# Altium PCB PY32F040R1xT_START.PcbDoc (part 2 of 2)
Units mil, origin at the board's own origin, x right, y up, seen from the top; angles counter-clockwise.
Board outline 1771.65 x 3925.12 mil, 2 copper layers (Top Layer, Bottom Layer), stack 21 mil thick; 156 components, 167 nets, 616 pads, 288 vias.
Unrouted connection lines stored in the file: 5.
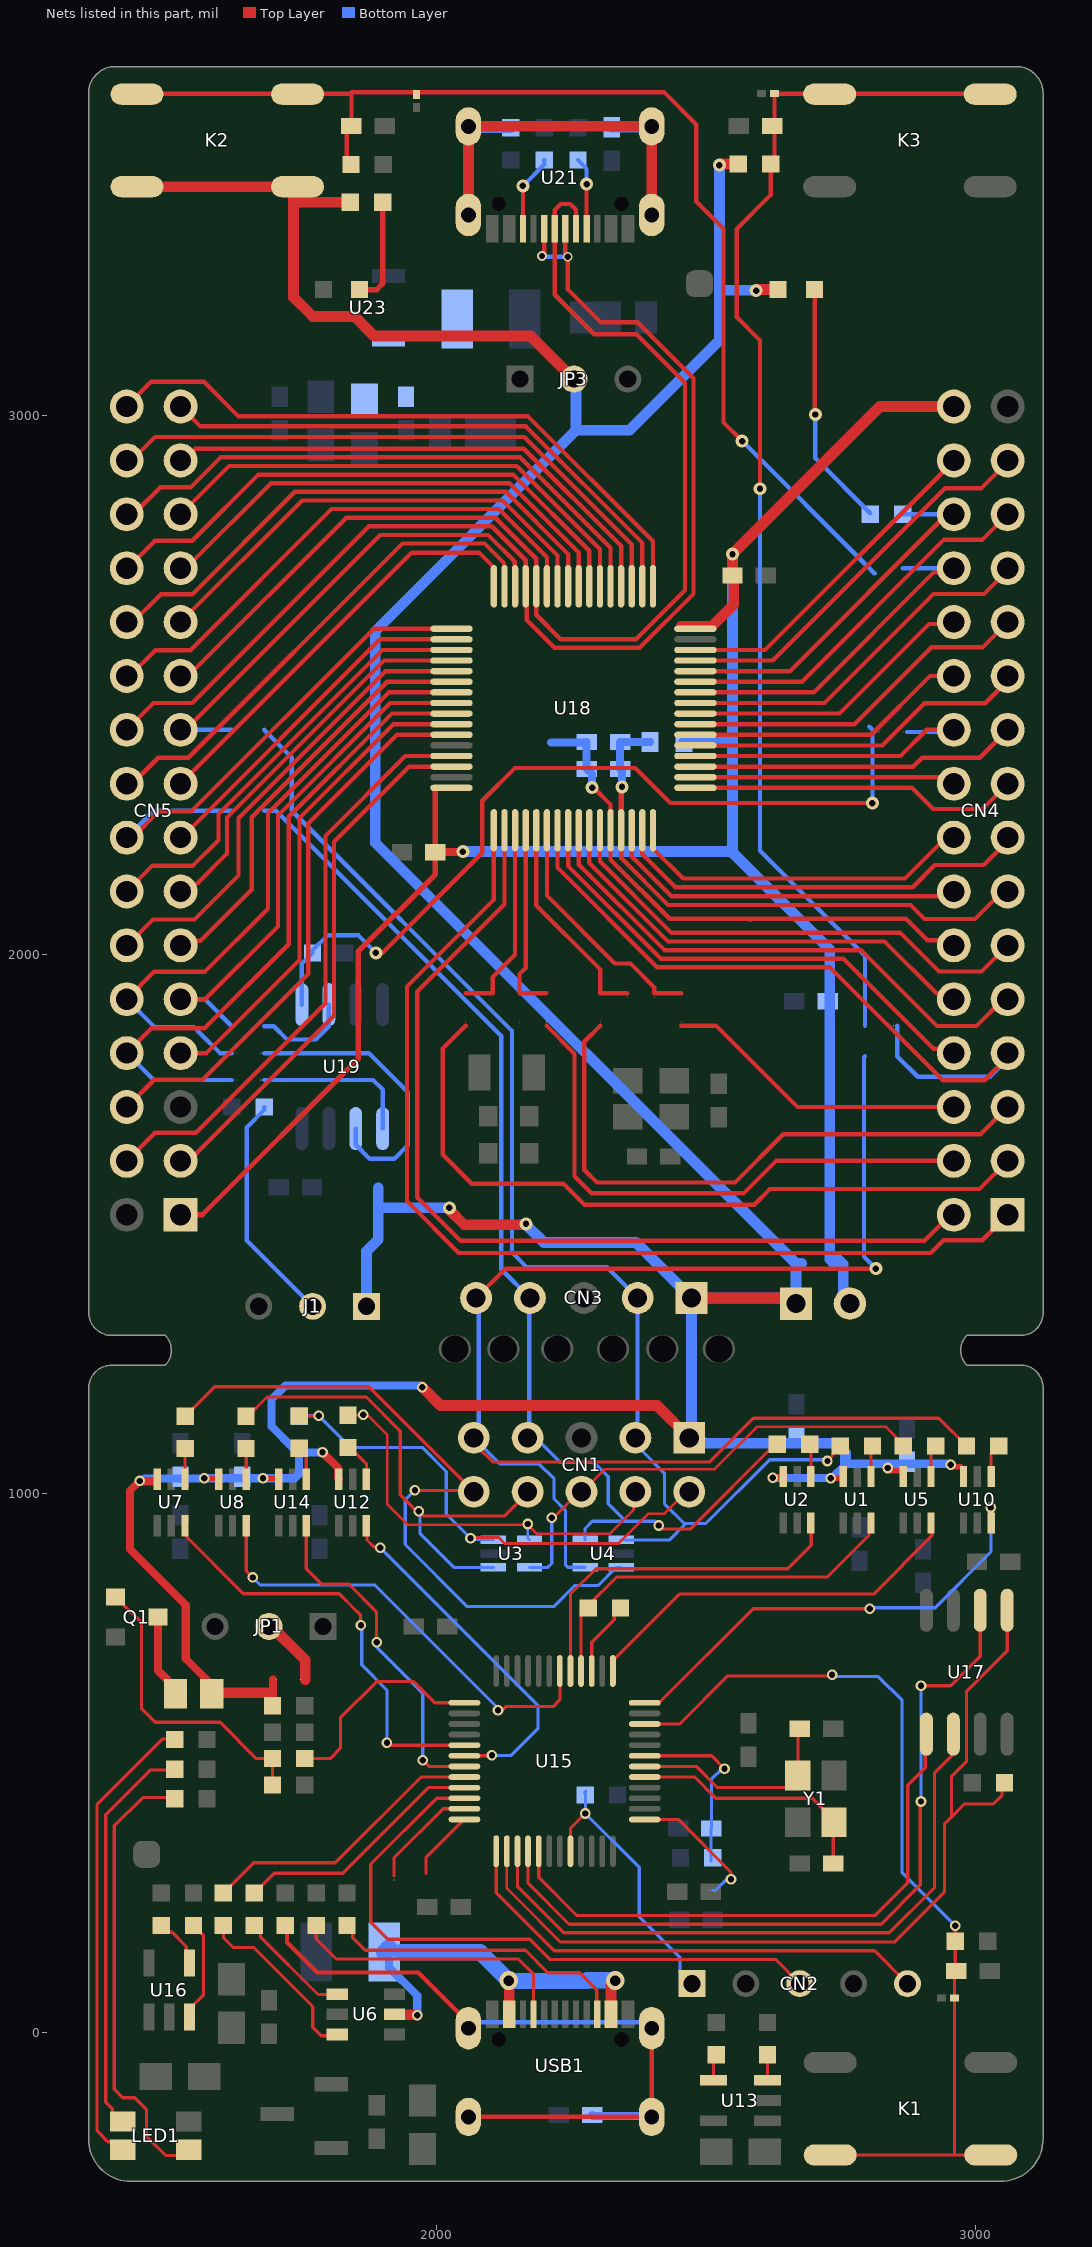
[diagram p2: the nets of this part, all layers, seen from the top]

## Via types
v1: diameter 24, hole 12, Top Layer to Bottom Layer, tented both sides, 117 vias
v2: diameter 19.68, hole 11.81, Top Layer to Bottom Layer, tented both sides, 109 vias
v3: diameter 19.68, hole 11.81, Top Layer to Bottom Layer, 41 vias
v4: diameter 35, hole 20, Top Layer to Bottom Layer, tented both sides, 15 vias
v5: diameter 17.72, hole 11.81, Top Layer to Bottom Layer, tented both sides, 2 vias
v6: diameter 30, hole 15, Top Layer to Bottom Layer, tented both sides, 2 vias
v7: diameter 40, hole 20, Top Layer to Bottom Layer, tented both sides, 2 vias

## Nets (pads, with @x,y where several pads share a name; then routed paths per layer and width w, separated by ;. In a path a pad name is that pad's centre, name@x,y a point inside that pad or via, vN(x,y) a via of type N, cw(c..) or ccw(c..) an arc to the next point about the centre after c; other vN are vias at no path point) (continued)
NetC34_2: C34.2 K3.1 R51.2 R52.1 U20.1 | length 2260.3
  Top Layer w8: v1(2600.24,2864.39) 2600.24,3139.79 2557.01,3183.01 2557.01,3346.47 2620,3409.45 2620,3464.12 R51.2@2620,3467.24 ; R51.2@2623.12,3464.12 2627.3,3468.3 U20.1@2627.3,3598 2627.95,3597.35 3026.9,3597.35 K3.1@3027.55,3596.7
  Bottom Layer w8: v1(2600.24,2864.39) 2600.24,2192.48 2795,1997.72 2795,1868
NetC35_2: C35.2 K2.1 R53.1 R54.2 U22.1 | length 2245.4
  Top Layer w8: K2.1@1444,3596.7 1444.65,3597.35 1742,3597.35 1842,3597.35 C35.2@1842,3538 ; R54.2@1833.14,3468.87 1833.14,3529.14 C35.2@1842,3538 ; R54.2@1841,3466.26 R54.2@1853,3454.26 ; v1(2567.19,2952.83) 2532.54,2987.49 2532.54,3346.86 2481.86,3397.53 2481.86,3540.74 2422.03,3600.57 1842.28,3600.57 1842,3600.29 C35.2@1842,3538
  Bottom Layer w8: v1(2567.19,2952.83) 2800.42,2719.61 2801,2719.61 2801,2719 2812.39,2707.61 2813,2707.61
NetC38_2: C38.2 C39.2 FUSE2.2 U23.3
NetC40_2: C40.2 R7.1 USB1.1 USB1.2 USB1.3 USB1.4 | length 1406.9
  Top Layer w8: R7.1@1719,198 1722.29,194.71 1722.29,166.87 1778.64,110.52 1965.97,110.52 2059.12,17.37 USB1.1@2059.12,7.29 ; USB1.3@2059.12,-157.27 USB1.4@2399.28,-157.27 USB1.2@2399.28,7.29
  Bottom Layer w8: USB1.1@2070.04,18.21 USB1.2@2388.36,18.21
  Bottom Layer w15: C40.2@2289,-154 2290.64,-155.64 2397.64,-155.64 USB1.4@2399.28,-157.27
  Bottom Layer w20: USB1.1@2059.12,7.29 USB1.1@2070.04,18.21 ; USB1.2@2388.36,18.21 USB1.2@2399.28,7.29
NetC41_2: C41.2 R57.2 U21.1 U21.2 U21.3 U21.4 | length 832
  Top Layer w20: U21.2@2059.12,3372.52 U21.4@2059.12,3537.08 U21.3@2399.28,3537.08 U21.1@2399.28,3372.52 U21.1@2399.28,3380.89
  Bottom Layer w20: U21.4@2059.12,3537.08 2061.7,3534.5 R57.2@2137.5,3534.5 ; C41.2@2325,3535.5 2397.69,3535.5 U21.3@2399.28,3537.08
NetJ1_2: J1.2 R41.1 | length 433.9
  Bottom Layer w8: R41.1@1680,1717 1680,1711.41 1647.74,1679.15 1647.74,1469.39 J1.2@1770,1347.13
NetLED1_2: LED1.2 R8.1 | length 846.1
  Top Layer w6: R8.1@1514,433 1511.67,435.33 1454.33,435.33 1402,383 1402,-106 1417.8,-121.8 1439.86,-121.8 1461.53,-143.47 1461.53,-192.84 1497.82,-229.13 1529.08,-229.13 LED1.2@1540.02,-218.18
NetLED1_3: LED1.3 R5.1 | length 884.3
  Top Layer w6: LED1.3@1398.28,-218.48 LED1.3@1412.98,-233.18 ; LED1.3@1417.98,-218.18 1403.28,-203.48 1390.09,-203.48 1370,-183.39 1370,423.34 1490.59,543.93 1513.07,543.93 R5.1@1514,543
NetLED1_4: LED1.4 R4.1 | length 755.1
  Top Layer w6: LED1.4@1410.66,-178.5 1398.36,-166.19 1398.36,-142.26 1386,-129.91 1386,403.34 1469.39,486.73 1512.73,486.73 R4.1@1514,488
NetLED2_VDD*_1: LED2_VDD*.1 R59.1 | length 198.6
  Top Layer w10: LED2_VDD*.1@1857,3234 1889,3234 1900,3245 R59.1@1900,3396
NetLED3_PB2_2: LED3_PB2.2 R46.1 | length 460.1
  Top Layer w8: LED3_PB2.2@2701.06,3235.88 2702.06,3234.88 2702.06,3005.95 v1@2703.04,3004.97
  Bottom Layer w8: v1@2703.04,3004.97 2703.04,2920.9 R46.1@2805.06,2818.88
  other v1: 2703.22,3002.23
NetQ1_1: Q1.1 R18.1 R19.2 | length 559
  Top Layer w6: Q1.1@1404,807.8 1405.97,807.8 1417.72,796.06 1417.72,794.23 1452.46,759.49 1452.46,600.34 1477.86,574.94 1598.45,574.94 1665.61,507.78 R18.1@1695.53,507.78 ; R19.2@1695.52,458.88 R18.1@1695.52,507.77
NetQ1_3: Q1.3 R14.1 | length 166.5
  Top Layer w6: Q1.3@1479.49,767.15 Q1.3@1482.74,770.4 ; R14.1@1515.54,628 R14.1@1515.54,633.91
  Top Layer w15: Q1.3@1482.74,770.4 1482.74,671.28 1515.54,638.49 R14.1@1515.54,628
NetR1_2: R1.2 USB1.A5 | length 530.2
  Top Layer w6: R1.2@1776.49,197.99 1776.49,172.82 1813.51,135.79 2151.58,135.79 2180.13,107.25 USB1.A5@2180.13,33.03
NetR2_1: R2.1 U1.4 | length 57.9
  Top Layer w6: U1.4@2806.23,1031.31 2806.23,1085.02 R2.1@2809.21,1088
NetR3_1: R3.1 USB1.B5 | length 566
  Top Layer w6: R3.1@1834,198 1844.31,187.69 1844.31,175.34 1867.85,151.8 2165.11,151.8 2206.66,110.24 2265.55,110.24 2297.17,78.62 2297.17,33.82 USB1.B5@2298.1,32.89
NetR6_1: R6.1 U2.4 | length 57.8
  Top Layer w6: R6.1@2692.06,1088 2694.8,1085.27 U2.4@2694.8,1031.31
NetR9_1: R9.1 U5.4 | length 60.3
  Top Layer w6: U5.4@2917.66,1031.31 2917.66,1079.3 R9.1@2926.35,1088
NetR10_1: R10.1 U6.3 | length 332.9
  Top Layer w6: R10.1@1604,198 1604.77,197.23 1604.77,174.69 1622.41,157.05 1660.8,157.05 1770.24,47.61 1770.24,8.87 1785.63,-6.52 1813.74,-6.52 U6.3@1815.53,-4.72
NetR11_1: R11.1 U6.1 | length 227.7
  Top Layer w6: R11.1@1662.75,203 1673.15,192.6 1673.15,176.68 1780,69.83 U6.1@1825.97,69.83
NetR12_1: R12.1 U7.4 | length 59
  Top Layer w6: R12.1@1527.55,1083 1533.14,1077.41 U7.4@1533.14,1026.31
NetR13_1: R13.1 U8.4 | length 60.8
  Top Layer w6: R13.1@1634.94,1083.02 R13.1@1644.82,1073.14 ; U8.4@1646.86,1026.31 R13.1@1646.86,1073.12
NetR17_1: R17.1 U10.4 | length 62.7
  Top Layer w6: U10.4@3029.08,1031.31 3029.08,1073.59 R17.1@3043.49,1088
NetR21_1: R21.1 U12.4 | length 75.3
  Top Layer w6: R21.1@1835.63,1085.11 1839.62,1085.11 1869.71,1055.03 U12.4@1869.71,1026.31
NetR23_2: R23.2 U13.4 | length 49.6
  Top Layer w6: U13.4@2514,-89.5 2514,-47 R23.2@2519,-42
NetR24_2: R24.2 U13.3 | length 47.5
  Top Layer w6: U13.3@2614,-89.5 R24.2@2614,-42
NetR25_1: R25.1 U14.4 | length 62.8
  Top Layer w6: R25.1@1745.2,1083.7 1758.28,1070.62 U14.4@1758.28,1026.31
NetR26_2: R26.2 U15.1 | length 256.3
  Top Layer w6: U15.1@2386.32,394.73 2448.18,394.73 2546.46,296.45 v3(2546.46,283.88)
  Bottom Layer w6: 2512.34,262.83 2517.61,262.83 2538.66,283.88 v3(2546.46,283.88)
NetR28_2: R28.2 U16.4 | length 96.1
  Top Layer w6: R28.2@1489,198 1501,186 1508.44,186 1535.5,158.94 1535.5,134 U16.4@1541.5,128
NetR29_2: R29.2 U16.3 | length 188.5
  Top Layer w6: U16.3@1541.5,28 1541.5,43 1567.56,69.06 1567.56,178.68 1561,185.24 1561,186 R29.2@1549,198
NetR30_1: R30.1 U15.36 | length 129.6
  Top Layer w6: 1980.21,294.75 1980.21,323.26 U15.36@2051.68,394.73
NetR32_1: R32.1 U15.35 | length 201.4
  Top Layer w6: 1920.96,290.4 1920.96,323.38 2012,414.42 U15.35@2051.68,414.42
NetR45_1: R45.1 R47.1 U19.1 | length 1545.9
  Top Layer w8: v1(1887.54,2003.05) 1899.05,2003.05 2084.81,2188.81 2084.81,2285.5 2145.39,2346.08 2368.77,2346.08 2433.55,2281.3 v1@2808.7,2281.3
  Bottom Layer w8: U19.1@1750,1907 1750,1983.14 R45.1@1769.57,2002.7 1769.57,2007.76 1797.31,2035.5 1855.09,2035.5 v1(1887.54,2003.05) ; 2803.28,2422.72 2813,2413 2809,2409 v1(2809,2281)
NetR48_1: R48.1 U19.2 | length 180.8
  Bottom Layer w8: 1680,1867 1697.74,1867 1722.33,1842.41 1776.1,1842.41 1800,1866.31 U19.2@1800,1907
NetR49_2: R49.2 U19.6 | length 543.1
  Bottom Layer w8: 1680,1817 1874.09,1817 1946.85,1744.24 1946.85,1646.27 1921.64,1621.07 1875.72,1621.07 1850,1646.79 U19.6@1850,1677
NetR50_2: R50.2 U19.5 | length 299.6
  Bottom Layer w8: 1680,1767 1882.25,1767 1900,1749.25 U19.5@1900,1677
NetR55_1: R55.1 U21.A5 | length 134.2
  Top Layer w8: U21.A5@2278.41,3346.92 v1(2278.41,3429.98)
  Bottom Layer w8: R55.1@2262.5,3474.5 2278.41,3458.59 v1(2278.41,3429.98)
NetR56_2: R56.2 U21.B5 | length 144
  Top Layer w8: U21.B5@2160.3,3346.92 v1(2160.3,3426.54)
  Bottom Layer w8: v1(2160.3,3426.54) 2200,3466.24 R56.2@2200,3474.5
NRST: CN4.7 R39.2 R52.2 U18.7 | length 1395.9
  Top Layer w8: U18.7@2224.47,2230.63 2224.47,2161.3 2409.62,1976.15 2730.25,1976.15 2939.65,1766.75 3017.3,1766.75 3060,1809.45 CN4.7@3060,1817
  Bottom Layer w8: 2855,1868 2855,1811 2893,1773 3027,1773 3060,1806 CN4.7@3060,1817
OSC32_IN: R42.1 R61.1 U18.3 | length 369.9
  Top Layer w8: 2054,1928 2104,1928 2104,1957.77 2145.73,1999.5 U18.3@2145.73,2230.63
OSC32_OUT: R43.1 R62.1 U18.4 | length 357.4
  Top Layer w8: U18.4@2165.42,2230.63 2165.42,1975.06 2154,1963.64 2154,1928 2204,1928
OSC_IN: R36.2 R63.1 U18.5 | length 401.9
  Top Layer w8: U18.5@2185.1,2230.63 2185.1,2091.22 2304,1972.32 2304,1928 2354,1928
OSC_OUT: R40.2 R64.1 U18.6 | length 452
  Top Layer w8: U18.6@2204.79,2230.63 2204.79,2109.32 2330.84,1983.27 2359.64,1983.27 2404,1938.91 2404,1928 2454,1928
PA0: CN4.14 U18.14 | length 680.8
  Top Layer w8: U18.14@2362.27,2230.63 2362.27,2181.89 2436.16,2108 2951,2108 CN4.14@2960,2117
PA1: CN4.15 U18.15 | length 789.8
  Top Layer w8: U18.15@2381.95,2230.63 2381.95,2186.18 2443.17,2124.96 2883.59,2124.96 2924.62,2165.99 3015.52,2165.99 3060,2210.47 CN4.15@3060,2217
PA2: CN4.16 U18.16 | length 646.7
  Top Layer w8: U18.16@2401.64,2230.63 2401.64,2197.04 2457.72,2140.96 2869.52,2140.96 2945.56,2217 CN4.16@2960,2217
PA3: CN4.17 U18.17 | length 615.5
  Top Layer w8: U18.17@2480.37,2309.36 2882.49,2309.36 2921.91,2269.94 3012.94,2269.94 CN4.17@3060,2317
PA4: CN4.20 R47.2 U18.20 | length 588.3
  Top Layer w8: U18.20@2480.37,2368.42 2861.28,2368.42 2909.86,2417 CN4.20@2960,2417
  Bottom Layer w8: 2873.11,2413.11 2956.11,2413.11 CN4.20@2960,2417
PA5: CN4.21 U18.21 | length 638.3
  Top Layer w8: U18.21@2480.37,2388.1 2827.1,2388.1 2905.38,2466.38 3018.38,2466.38 3060,2508 CN4.21@3060,2517
PA6: CN4.22 U18.22 | length 524.9
  Top Layer w8: U18.22@2480.37,2407.79 2806.79,2407.79 2916,2517 CN4.22@2960,2517
PA7: CN4.23 U18.23 | length 658.1
  Top Layer w8: U18.23@2480.37,2427.47 2775.53,2427.47 2918.07,2570.02 3012.98,2570.02 CN4.23@3060,2617
PA8: CN5.24 U18.41 | length 1027
  Top Layer w8: CN5.24@1425,2617 1436.86,2617 1488.6,2668.74 1546.74,2668.74 1736.7,2858.7 2128.8,2858.7 2244.16,2743.34 U18.41@2244.16,2683.37
PA9: CN5.23 U18.42 | length 892.4
  Top Layer w8: CN5.23@1525,2617 1750.7,2842.7 2122.17,2842.7 2224.47,2740.4 U18.42@2224.47,2683.37
PA10: CN5.22 U18.43 | length 999.1
  Top Layer w8: CN5.22@1425,2517 1430.19,2517 1477.71,2564.52 1542.68,2564.52 1804.86,2826.7 2115.54,2826.7 2204.79,2737.46 U18.43@2204.79,2683.37
PA11: CN5.21 U18.44 U21.A7 U21.B7 | length 2185.1
  Top Layer w8: CN5.21@1525,2517 1538.93,2517 1832.63,2810.7 2108.91,2810.7 2185.1,2734.52 2185.1,2630.43 2230.29,2585.24 2370.24,2585.24 2461,2676 2461,3061.16 2370.82,3151.34 2292.57,3151.34 2219.36,3224.55 U21.A7@2219.36,3346.92 2219.36,3381.7 2230.63,3392.98 2247.99,3392.98 2258.73,3382.24 U21.B7@2258.73,3346.92
PA12: CN5.20 U18.45 U21.A6 U21.B6 | length 2329.4
  Top Layer w8: CN5.20@1425,2417 1425,2427 1435,2427 1474.77,2466.77 1546.4,2466.77 1874.34,2794.7 2102.29,2794.7 2165.42,2731.57 U18.45@2165.42,2683.37 2166.15,2682.64 2166.15,2646.48 2167.19,2645.44 2167.19,2621.06 2219.02,2569.24 2376.87,2569.24 2477,2669.37 2477,3069.58 2373.38,3173.2 2304.98,3173.2 2243.19,3234.99 v5(2243.19,3295.14) 2239.04,3299.3 U21.A6@2239.04,3346.92 ; v5(2195.65,3296.43) 2199.67,3300.45 U21.B6@2199.67,3346.92
  Bottom Layer w8: v5(2195.65,3296.43) 2197.06,3295.01 2197.2,3295.14 v5(2243.19,3295.14)
PA13: CN5.19 R37.2 U18.46 | length 931.6
  Top Layer w8: CN5.19@1525,2417 1533.86,2417 1895.57,2778.7 2095.66,2778.7 2145,2729.36 2145,2684.1 U18.46@2145.73,2683.37
  Bottom Layer w8: CN5.19@1525,2417 1620,2417
PA14: CN5.16 R38.2 U18.49 | length 978.9
  Top Layer w8: CN5.16@1425,2217 1436.02,2217 1485.11,2266.09 1545.28,2266.09 1883.83,2604.64 U18.49@2027.63,2604.64
  Bottom Layer w8: CN5.16@1425,2217 1475,2267 1620,2267
PA15: CN5.15 U18.50 | length 655
  Top Layer w8: CN5.15@1525,2217 1527.31,2217 1895.26,2584.95 U18.50@2027.63,2584.95
PB0: CN4.26 R53.2 U18.26 | length 670.1
  Top Layer w8: U18.26@2480.37,2486.53 2699.9,2486.53 2922.43,2709.06 2952.06,2709.06 CN4.26@2960,2717
  Bottom Layer w8: 2865,2717 CN4.26@2960,2717
PB1: CN4.27 U18.27 | length 708.4
  Top Layer w8: U18.27@2480.37,2506.21 2678.06,2506.21 2941.85,2770 3013,2770 CN4.27@3060,2817
PB2: CN4.28 R46.2 U18.28 | length 701.6
  Top Layer w8: U18.28@2480.37,2525.9 2655.9,2525.9 2947,2817 CN4.28@2960,2817
  Bottom Layer w8: R46.2@2865,2817 CN4.28@2960,2817 CN4.28@2955.5,2812.5
PB3: CN5.10 R49.1 U18.55 | length 1178.9
  Top Layer w8: CN5.10@1425,1917 1476.21,1968.21 1570.35,1968.21 1686.97,2084.83 1686.97,2262.25 1911.26,2486.53 U18.55@2027.63,2486.53
  Bottom Layer w8: CN5.10@1425,1917 1476.7,1865.3 1549.73,1865.3 1562.88,1852.15 1598.03,1817 1620,1817
PB4: CN5.9 R48.2 U18.56 | length 966.8
  Top Layer w8: CN5.9@1525,1917 1570.49,1917 1705.65,2052.15 1705.65,2258.29 1914.2,2466.84 U18.56@2027.63,2466.84
  Bottom Layer w8: CN5.9@1525,1917 1570,1917 1620,1867
PB5: CN5.8 R50.1 U18.57 | length 1217.9
  Top Layer w8: CN5.8@1425,1817 1471,1863 1569.53,1863 1725.52,2018.99 1725.52,2255.54 1917.14,2447.16 U18.57@2027.63,2447.16
  Bottom Layer w8: CN5.8@1425,1817 1475,1767 1620,1767
PB6: CN5.7 U18.58 | length 909.8
  Top Layer w8: CN5.7@1525,1817 1573.07,1817 1745.71,1989.65 1745.71,2253.1 1920.08,2427.47 U18.58@2027.63,2427.47
PB7: CN5.6 U18.59 | length 1052.4
  Top Layer w8: CN5.6@1425,1717 1425.62,1717 1476.12,1767.5 1565.36,1767.5 1761.71,1963.85 1761.71,2243.2 1926.3,2407.79 U18.59@2027.63,2407.79
PB8: CN5.4 U18.61 | length 1095.8
  Top Layer w8: CN5.4@1425,1617 1477,1669 1553.03,1669 1793.71,1909.68 1793.71,2220.2 1941.94,2368.42 U18.61@2027.63,2368.42
PB9: CN5.3 U18.62 | length 994.7
  Top Layer w8: CN5.3@1525,1617 1539.88,1617 1555.02,1632.14 1555.38,1632.14 1809.71,1886.47 1809.71,2209.14 1949.31,2348.73 U18.62@2027.63,2348.73
PB10: CN4.29 U18.29 | length 735.1
  Top Layer w8: U18.29@2480.37,2545.58 2623.94,2545.58 2943.92,2865.56 3011.32,2865.56 3060,2914.24 CN4.29@3060,2917
PB11: CN4.30 U18.30 | length 626.2
  Top Layer w8: U18.30@2480.37,2565.27 2609.69,2565.27 2960,2915.58 CN4.30@2960,2917
PB12: CN5.32 U18.33 | length 1202.4
  Top Layer w8: CN5.32@1425,3017 1425,3018.08 1469.85,3062.93 1568.24,3062.93 1632.35,2998.81 2169.71,2998.81 2401.64,2766.88 U18.33@2401.64,2683.37
PB13: CN5.31 U18.34 | length 1042.3
  Top Layer w8: CN5.31@1525,3017 1561.75,2980.25 2165.64,2980.25 2381.95,2763.94 U18.34@2381.95,2683.37
PB14: CN5.30 U18.35 | length 1115.5
  Top Layer w8: CN5.30@1425,2917 1433.75,2917 1477.24,2960.5 1853.5,2960.5 2162.77,2960.5 2362.27,2761 U18.35@2362.27,2683.37
PB15: CN5.29 U18.36 | length 978.4
  Top Layer w8: CN5.29@1525,2917 1527.82,2914.18 1552.34,2938.7 2161.93,2938.7 2342.58,2758.06 U18.36@2342.58,2683.37
PC0: CN4.8 U18.8 | length 926.1
  Top Layer w8: U18.8@2244.16,2230.63 2244.16,2164.24 2416.25,1992.15 2755.24,1992.15 2922.44,1824.95 2952.05,1824.95 CN4.8@2960,1817
PC1: CN4.9 U18.9 | length 1004.3
  Top Layer w8: U18.9@2263.84,2230.63 2263.84,2167.18 2422.88,2008.15 2787.96,2008.15 2928.7,1867.41 3002.03,1867.41 3051.62,1917 CN4.9@3060,1917
PC2: CN4.10 U18.10 | length 841.8
  Top Layer w8: U18.10@2283.53,2230.63 2283.53,2170.12 2429.5,2024.15 2831.51,2024.15 2928.14,1927.52 2949.48,1927.52 CN4.10@2960,1917
PC3: CN4.11 U18.11 | length 919.3
  Top Layer w8: U18.11@2303.21,2230.63 2303.21,2173.07 2436.13,2040.15 2860.81,2040.15 2932.58,1968.37 3011.37,1968.37 CN4.11@3060,2017
PC4: CN4.24 U18.24 | length 550
  Top Layer w8: U18.24@2480.37,2447.16 2747.76,2447.16 2914.11,2613.5 2956.5,2613.5 CN4.24@2960,2617
PC5: CN4.25 U18.25 | length 685.6
  Top Layer w8: U18.25@2480.37,2466.84 2719.99,2466.84 2922.26,2669.11 3016.12,2669.11 3060,2712.99 CN4.25@3060,2717
PC6: CN5.28 U18.37 | length 1082.8
  Top Layer w8: CN5.28@1425,2817 1437.04,2817 1486.99,2866.94 1543.24,2866.94 1599.01,2922.7 2155.31,2922.7 2322.9,2755.11 U18.37@2322.9,2683.37
PC7: CN5.27 U18.38 | length 948.2
  Top Layer w8: CN5.27@1525,2817 1525.6,2817.6 1614.7,2906.7 2148.68,2906.7 2303.21,2752.17 U18.38@2303.21,2683.37
PC8: CN5.26 U18.39 | length 1054.9
  Top Layer w8: CN5.26@1425,2717 1426.2,2717 1477.22,2768.03 1546.55,2768.03 1669.23,2890.7 2142.05,2890.7 2283.53,2749.23 U18.39@2283.53,2683.37
PC9: CN5.25 U18.40 | length 920.3
  Top Layer w8: CN5.25@1525,2717 1529.91,2721.91 1539.76,2721.91 1692.56,2874.7 2135.42,2874.7 2263.84,2746.29 U18.40@2263.84,2683.37
PC10: CN5.14 U18.51 | length 816.8
  Top Layer w8: CN5.14@1425,2117 1473,2165 1547.93,2165 1595.1,2212.17 1595.1,2260.88 1899.49,2565.27 U18.51@2027.63,2565.27
PC11: CN5.13 U18.52 | length 719.4
  Top Layer w8: CN5.13@1525,2117 1539.88,2117 1554.69,2131.81 1555.7,2131.81 1611.1,2187.21 1611.1,2254.25 1902.43,2545.58 U18.52@2027.63,2545.58
PC12: CN5.12 U18.53 | length 875.6
  Top Layer w8: CN5.12@1425,2017 1425.95,2017 1473.95,2065 1550.57,2065 1632.48,2146.91 1632.48,2253 1905.37,2525.9 U18.53@2027.63,2525.9
PC13: CN4.2 U18.2 | length 1797.9
  Top Layer w8: U18.2@2126.05,2230.63 2126.05,2093.24 1964,1931.19 1964,1549.22 2044.54,1468.67 2905.74,1468.67 2954.07,1517 CN4.2@2960,1517
PC14: CN4.3 R61.2 | length 1377.8
  Top Layer w8: 2054,1868 2011.47,1825.47 2011.47,1628.57 2065.35,1574.7 2235.53,1574.7 2274.57,1535.66 2589.66,1535.66 2618.65,1564.65 3007.65,1564.65 CN4.3@3060,1617
PC15: CN4.4 R62.2 | length 1043.1
  Top Layer w8: 2204,1868 2256,1816 2256,1588.65 2287.93,1556.73 2569.73,1556.73 2630,1617 CN4.4@2960,1617
PF0: CN4.5 R63.2 | length 1133.5
  Top Layer w8: 2304,1868 2274.14,1838.14 2274.14,1600.64 2297.93,1576.85 2553.85,1576.85 2643.46,1666.46 3009.46,1666.46 CN4.5@3060,1717
PF1: CN4.6 R64.2 | length 568.5
  Top Layer w8: 2454,1868 2518.75,1868 2669.75,1717 CN4.6@2960,1717
PF3: CN4.18 U18.18 | length 484.6
  Top Layer w8: U18.18@2480.37,2329.05 2933.07,2329.05 2945.12,2317 CN4.18@2960,2317
PF4: CN4.19 U18.19 | length 607.9
  Top Layer w8: U18.19@2480.37,2348.73 2884.86,2348.73 2901.33,2365.2 3008.2,2365.2 CN4.19@3060,2417
PF5: CN5.18 U18.47 | length 943.3
  Top Layer w8: CN5.18@1425,2317 1435.31,2317 1483.57,2365.26 1539.18,2365.26 1936.63,2762.7 2089.03,2762.7 2125.32,2726.42 2125.32,2684.1 U18.47@2126.05,2683.37
PF6: CN5.17 U18.48 | length 805.3
  Top Layer w8: CN5.17@1525,2317 1953.94,2745.94 2078.57,2745.94 2106.3,2718.21 2106.3,2683.43 U18.48@2106.36,2683.37
PF7: CN5.11 U18.54 | length 784
  Top Layer w8: CN5.11@1525,2017 1533.5,2025.5 1562.02,2025.5 1657.02,2120.5 1657.02,2254.91 1908.31,2506.21 U18.54@2027.63,2506.21
PF9: CN4.1 U18.1 | length 1939.4
  Top Layer w8: U18.1@2106.36,2230.63 2106.36,2101.9 1945,1940.54 1945,1542.34 2041.27,1446.07 2917.27,1446.07 2940.92,1469.73 3012.73,1469.73 CN4.1@3060,1517
PYLK_BOOT0: CN2.1 R27.1 U15.44 | length 522.7
  Top Layer w6: U15.44@2248.53,335.68 2248.53,378.07 v2(2276.21,405.75)
  Bottom Layer w6: R27.1@2277.26,447.4 2274.49,444.63 2276.21,442.9 v2(2276.21,405.75) 2376,305.96 2376,214 2451.96,138.04 2451.96,112.04 CN2.1@2474,90
PYLK_KEY: C5.2 K1.2 R15.1 U11.1 U15.10 | length 1779.6
  Top Layer w6: U15.10@2386.32,571.9 2451.14,571.9 2540.44,661.2 2732.2,661.2 v2(2734,663) ; K1.2@2730.55,-228 2992.3,-228 3007.51,-228 K1.2@2993.02,-242.49 ; C5.2@2961.3,110.7 U11.1@2961.3,63 2961.3,-228 K1.2@3028.55,-228 ; v2(2962.39,197.54) 2962.76,197.17 R15.1@2962.76,168.85 C5.2@2962.76,115.49
  Bottom Layer w6: v2(2734,663) 2737.06,659.94 2746.62,659.94 2746.69,659.88 2819.92,659.88 2864,615.8 2864,295.93 v2(2962.39,197.54)
PYLK_NRST: C23.2 R35.1 U15.7 | length 341.9
  Top Layer w6: U15.7@2386.32,512.84 2510.36,512.84 v2(2534.4,488.8)
  Bottom Layer w6: R35.1@2509.12,318 2509.12,377 C23.2@2510.12,378 2510.12,469 2529.92,488.8 v2(2534.4,488.8)
PYLK_OSCIN: C18.2 U15.5 Y1.3 | length 465.6
  Top Layer w6: U15.5@2386.32,473.47 2479.05,473.47 2518.42,434.1 2697.11,434.1 2737.59,393.63 Y1.3@2737.59,389.69 2736.12,388.22 C18.2@2736.12,313
PYLK_OSCOUT: C24.2 U15.6 Y1.1 | length 399.8
  Top Layer w6: U15.6@2386.32,493.16 2481.99,493.16 2521.36,453.79 2651.03,453.79 2670.66,473.41 Y1.1@2670.66,476.31 2670.66,559.54 C24.2@2674.12,563
PYLK_SPI_CS: R34.1 U15.38 U17.1 | length 1667.6
  Top Layer w5: U15.38@2130.42,335.68 2130.42,266.62 2191.66,205.38
  Top Layer w6: 2191.66,205.38 2229.95,167.09 2849.51,167.09 2942.88,260.47 2942.88,386.88 2955.77,399.77 ; R34.1@3054,463 3049.62,458.62 3049.62,439.69 3033.36,423.42 2979.42,423.42 2955.77,399.77 ; U17.1@3059,783 3059,708 2983.69,632.69 2983.69,503.01 2955.77,475.09 2955.77,399.77
PYLK_SPI_MISO: U15.40 U17.2 | length 1437.2
  Top Layer w6: U15.40@2169.79,335.68 2169.79,276.3 2245.8,200.3 2825,200.3 2897.9,273.2 2897.9,426.9 v2(2899,428) ; v2(2899,643) 2954,643 3009,698 U17.2@3009,783
  Bottom Layer w6: v2(2899,428) v2(2899,643)
PYLK_SPI_MOSI: U15.41 U17.5 | length 1077.9
  Top Layer w6: U15.41@2189.47,335.68 2189.47,287.49 2260.66,216.3 2813.42,216.3 2874.53,277.41 2874.53,458.09 2907.13,490.69 2907.13,551.13 U17.5@2909,553
PYLK_SPI_SCK: U15.39 U17.6 | length 1208.9
  Top Layer w6: U15.39@2150.1,335.68 2150.1,270.36 2210.32,210.14 2236.17,184.3 2840.07,184.3 2924.21,268.44 2924.21,481.06 2955.94,512.79 2955.94,549.94 U17.6@2959,553
SWD_SCK: CN2.5 U15.37 | length 910.1
  Top Layer w6: U15.37@2110.73,335.68 2110.73,258.75 2218.48,151 2813,151 CN2.5@2874,90
SWD_SDA: CN2.3 U15.34 | length 1175.6
  Top Layer w6: U15.34@2051.68,434.1 2000.11,434.1 1878.05,312.04 1878.05,203.71 1909.57,172.2 2172.75,172.2 2209.95,135 2629,135 CN2.3@2674,90
T_RESET: CN1.9 CN3.5 R17.2 R39.1 U4.4 | length 2794
  Top Layer w6: CN1.9@2076.78,1085.78 2104.2,1058.36 2506.91,1058.36 2587.99,1139.44 2932.06,1139.44 R17.2@2983.49,1088
  Top Layer w8: CN3.5@2073.26,1362.56 2127.65,1416.95 v1(2815.47,1416.95)
  Bottom Layer w6: CN1.9@2069,1103 2117.22,1054.78 2190.02,1054.78 2218.1,1026.69 2218.1,989.42 2239.15,968.37 2239.15,867.31 2243.61,862.85 2275.09,862.85 U4.4@2275.54,862.41
  Bottom Layer w8: CN1.9@2069,1103 2078.04,1112.04 2078.04,1357.78 CN3.5@2073.26,1362.56 ; 2795,1811 2793.46,1809.46 2793.46,1438.96 v1(2815.47,1416.95)
T_RESETa: U10.3 U15.12 | length 870.1
  Top Layer w6: U15.12@2386.32,611.27 2412.79,611.27 2587.47,785.96 2675.53,785.96 v2(2803.91,785.96) ; v2(3028.82,973.7) 3029.08,973.44 U10.3@3029.08,944.69
  Bottom Layer w6: v2(2803.91,785.96) 2805.65,787.7 2925.4,787.7 3028.82,891.11 v2(3028.82,973.7)
T_RTCK_DTRa: U5.3 U15.13 | length 731.2
  Top Layer w6: U15.13@2327.27,670.32 2327.27,689.57 2450.7,813 2810.99,813 2919.18,921.19 2919.18,943.16 U5.3@2917.66,944.69
T_RTCK_VCP_DTR: CN1.6 R9.2 U3.5 | length 868.3
  Top Layer w5: v2(2213.81,954.67) 2217.24,954.67 2265.57,1003 CN1.6@2269,1003 2270.63,1003 2312.49,1044.86 2515.73,1044.86 2594.3,1123.44 2833.98,1123.44 2854.35,1103.07 2854.35,1100 R9.2@2866.35,1088
  Bottom Layer w6: U3.5@2172.46,862.41 2206.51,862.41 2213.81,869.71 v2(2213.81,954.67)
T_TCK_SWCLK: CN1.7 CN3.4 R6.2 R38.1 U4.5 | length 2109
  Top Layer w6: CN1.7@2174,1113 CN1.7@2175.35,1114.35 ; v2(2412.5,940.32) 2419.14,933.69 2470.96,933.69 2625.28,1088 R6.2@2632.06,1088
  Bottom Layer w6: CN1.7@2176.5,1110.5 2229.47,1057.53 2291.65,1057.53 2318.6,1030.57 2318.6,980.54 2351.14,948 ; U4.5@2275.54,913.59 2275.54,934.54 2289,948 2351.14,948 ; v2(2412.5,940.32) 2404.82,948 2351.14,948
  Bottom Layer w8: 1680,2267 1701.97,2267 2119.97,1849 2119.97,1415.86 CN3.4@2173.26,1362.56 2171.79,1361.1 2171.79,1105.79 CN1.7@2169,1103
T_TCK_SWCLKa: U2.3 U15.17 | length 668.1
  Top Layer w5: U15.17@2248.53,670.32 2248.53,812.76 2295.77,860
  Top Layer w6: 2295.77,860 2401.62,860 2651.43,860 2695.41,903.98 2695.41,944.08 U2.3@2694.8,944.69
T_TDI_VCP_TX: CN1.4 R21.2 U3.4 | length 783.1
  Top Layer w5: R21.2@1835.63,1145.11 1871.9,1145.11 1908.54,1108.48 1908.54,979.62 1946.29,941.86 v2@2169,941.86 ; R21.2@1835.63,1148.11 R21.2@1837.13,1146.61 ; v2@2169.02,941.86 2185.78,925.11 2321.76,925.11 2365.56,968.9 2365.56,999.56 CN1.4@2369,1003
  Bottom Layer w5: v2@2169.06,942.94 2169.06,917 U3.4@2172.46,913.59
  other v2: 2169,943
  other v3: 1863.96,1145.98
T_TDI_VCP_TXa: U12.3 U15.30 | length 672
  Top Layer w6: U12.3@1869.71,939.69 1870.93,938.47 1870.93,913.37 1883.24,901.06 1893.56,901.06 v2(1895.31,899.31) ; U15.30@2051.68,512.84 2102.02,512.84 v2(2102.76,513.58)
  Bottom Layer w6: v2(1895.31,899.31) 2188.09,606.53 2188.09,562.77 2154.71,529.38 2138.91,513.58 v2(2102.76,513.58)
T_TDO_SWO: CN1.10 R12.2 U4.3 | length 1333.3
  Top Layer w6: R12.2@1533.66,1143.08 1588.47,1197.9 1874.1,1197.9 CN1.10@2062.51,1009.49 ; v2(1959.87,1005.75) 1960.54,1005.08 2058.1,1005.08 CN1.10@2062.51,1009.49 ; CN1.10@2069,1003 CN1.10@2062.51,1009.49
  Bottom Layer w6: v2(1959.87,1005.75) 1941.83,987.72 1941.83,905.08 2057.06,789.86 2217.29,789.86 2256.42,828.99 2300.45,828.99 2333.88,862.41 U4.3@2342.46,862.41 U4.3@2340.15,860.1
T_TDO_SWOa: U7.3 U15.29 | length 807.7
  Top Layer w6: U7.3@1533.14,939.69 1533.14,921.86 1641.46,813.54 1819.08,813.54 1825.63,807 1826.01,807 1843,790.01 1843,789.63 1858.93,773.7 1858.93,755.69 v2(1859.62,755) ; v2(1907.88,537.33) 1912.68,532.53 1995.55,532.53 U15.29@2051.68,532.53
  Bottom Layer w6: v2(1859.62,755) 1860.95,753.68 1860.95,681.93 1907.88,635 v2(1907.88,537.33)
T_TMS_SWDIO: CN1.3 CN3.2 R2.2 R37.1 U4.1 | length 2355.5
  Top Layer w6: CN1.3@2373.37,1089.19 CN1.3@2379.56,1083 ; v2@2725.62,1061.31 2736.21,1071.9 2736.21,1075 R2.2@2749.21,1088
  Bottom Layer w6: U4.1@2342.77,913.29 2431.45,913.29 2462.1,943.94 ; CN1.3@2377.59,1082.7 2422.86,1037.42 2422.86,980.89 2459.81,943.94 2462.1,943.94 ; v2(2725.43,1060.07) 2723.25,1062.25 2618.29,1062.25 2499.98,943.94 2462.1,943.94
  Bottom Layer w8: 1680,2417 1731.3,2365.7 1731.3,2266.83 2139.84,1858.29 2139.84,1447.46 2167.16,1420.15 2315.67,1420.15 CN3.2@2373.26,1362.56 2373,1362.3 2373,1107 CN1.3@2369,1103
T_TMS_SWDIOa: R31.1 U1.3 U15.16 | length 723.8
  Top Layer w6: U15.16@2268.21,670.32 R31.1@2268.21,790.37 ; R31.1@2281.46,787.37 2281.46,791.99 2334.12,844.65 2390.7,844.65 2725.22,844.65 2802.34,921.77 2802.34,940.8 U1.3@2806.23,944.69
T_TMS_SWDIOa_IN: R31.2 U15.15 | length 143.2
  Top Layer w6: U15.15@2287.9,670.32 2287.9,723.64 2329.82,765.56 R31.2@2329.82,796.16
T_TRST_RTSa: U8.3 U15.18 | length 840.3
  Top Layer w6: U8.3@1646.86,939.69 1646.86,855.86 v2(1658.82,843.9) ; v2(2113.92,597.35) 2117.83,593.44 2128.54,604.16 2216.39,604.16 2228.84,616.6 U15.18@2228.84,670.32
  Bottom Layer w6: v2(1658.82,843.9) 1672.81,829.91 1885.65,829.91 2113.92,601.64 v2(2113.92,597.35)
T_TRST_VCP_RTS: CN1.8 R13.2 U3.1 | length 935
  Top Layer w6: R13.2@1646.3,1143.1 1649.54,1143.1 1685.24,1178.8 1869.25,1178.8 1932.58,1115.47 1932.58,997.56 1963.4,966.73 v2(1966.86,966.73) 1975.6,958 2126.67,958 2174,1005.33 CN1.8@2174,1013
  Bottom Layer w6: v2(1966.86,966.73) 1969,964.6 1969,925.6 2032.19,862.41 U3.1@2105.54,862.41
T_VCP_RX: CN1.2 R22.1 R25.2 U3.3 | length 1000.9
  Top Layer w5: v2(2062.97,916.74) 2064.23,918 2115.42,918 2126.45,906.97 2337.91,906.97 2393.3,962.36 2423.36,962.36 CN1.2@2474,1013
  Top Layer w6: R25.2@1745.2,1143.7 1780.7,1143.7 v3(1781,1144) ; R25.2@1745.2,1154.85 R25.2@1745.32,1154.97
  Bottom Layer w6: R22.1@1745,1143 1746,1144 v3(1781,1144) 1839.72,1085.28 1973.26,1085.28 2018.05,1040.5 2018.05,961.66 v2(2062.97,916.74) 2062.23,916 2062.23,914.77 2104.36,914.77 U3.3@2105.54,913.59
T_VCP_RXa: U14.3 U15.31 | length 636
  Top Layer w6: U14.3@1758.28,939.69 1758.28,860.29 1787.27,831.3 1837.54,831.3 1888.4,780.43 1888.4,724.38 v2(1889,723.78) ; v2(1974.4,504.75) 1985.99,493.16 U15.31@2051.68,493.16
  Bottom Layer w6: v2(1889,723.78) 1889,714.42 1974.4,629.02 v2(1974.4,504.75)
TVDD: C11.2 C12.2 C13.2 C14.2 CN1.1 CN3.1 J1.1 JP2.1 JP3.2 K2.2 LED3_PB2.1 R14.2 R16.2 R22.2 R33.2 R44.1 R51.1 R58.1 R59.2 U1.6 U2.6 U5.6 U7.6 U8.6 U10.6 U12.6 U14.6 | length 8646.3
  Top Layer w6: U8.6@1595.67,1026.31 U8.6@1598.56,1029.2 ; U14.6@1707.1,1026.31 U14.6@1709.99,1029.2
  Top Layer w10: v2(1569,1028) 1593.98,1028 U8.6@1595.67,1026.31 ; v3@1679,1028 1705.41,1028 U14.6@1707.1,1026.31 ; v3(2731.88,1028.09) 2753.07,1028.09 2753.16,1028 2755.05,1029.89 U1.6@2755.05,1031.31 ; v2(2837.29,1047.06) 2842.61,1041.74 2866.47,1041.74 U5.6@2866.47,1031.31 ; v2@2962.68,1049.1 2972.91,1049.1 2977.9,1044.1 U10.6@2977.9,1031.31
  Top Layer w12: v2@2624.9,1029.9 U2.6@2643.01,1029.9
  Top Layer w15: v2(1449,1023) 1430.66,1004.66 1430.66,896.6 1534.53,792.73 1534.53,692.95 1574.52,652.96 1574.52,635.95 R14.2@1582.46,628 R14.2@1584.24,629.78 ; v2@1449.63,1022.37 U7.6@1481.35,1022.37 ; 1692.07,629.78 1696.08,625.77 ; R16.2@1696.08,597.02 1696.08,625.77 ; 1696.08,654.52 1696.08,625.77 ; v3(1788.28,1076.05) 1816.84,1047.49 1816.84,1028 U12.6@1818.53,1026.31 ; v2(2624,1029) v2@2624.9,1029.9
  Top Layer w20: K2.2@1444,3425 K2.2@1737.32,3425 ; R14.2@1584.24,629.78 1692.07,629.78 ; K2.2@1742,3425 1734.49,3417.49 1734.49,3392 ; R59.2@1840,3396 1738.49,3396 1734.49,3392 ; v3(1973.35,1197.16) 2007.41,1163.1 2408.9,1163.1 CN1.1@2469,1103 ; v1(2023.87,1529.85) 2023.87,1525.91 2051.44,1498.34 2161.51,1498.34 2162.41,1499.23 v1@2164.15,1499.23 ; JP3.2@2254.27,3068 2174.38,3147.9 1884.03,3147.9 1847.55,3184.38 1770.04,3184.38 1734.49,3219.93 1734.49,3392 ; CN3.1@2473.26,1362.56 2656.56,1362.56 JP2.1@2667,1352.13 ; v1(2525,3465) 2527.24,3467.24 R51.1@2560,3467.24 ; v1(2593,3232) 2595,3234 LED3_PB2.1@2634,3234
  Bottom Layer w15: v2(1449,1023) 1452.79,1023 1457.67,1027.88 C14.2@1522.87,1027.88 ; C14.2@1524,1026.74 C14.2@1522.87,1027.88 ; v2@1568.88,1027.88 C14.2@1522.87,1027.88 ; v2(1569,1028) v3(1677.77,1028) 1737,1028 1745,1036 R22.2@1745,1076.05 ; v3(1788.28,1076.05) R22.2@1745,1076.05 ; v3(1973.35,1197.16) 1970.13,1200.38 1719.38,1200.38 1694,1175 1694,1123.76 1734.76,1083 R22.2@1745,1083 R22.2@1745,1076.05 ; v2@2624.38,1028.62 v3@2731.36,1028.62 ; v3(2731.88,1028.09) 2733.15,1028.09 2735.49,1030.43 2736.09,1030.43 2760.58,1054.92 ; 2758.72,1054.92 2760.58,1054.92 ; v2(2954,1053) 2952.08,1054.92 2760.58,1054.92
  Bottom Layer w20: J1.1@1870,1347.13 1870,1449.46 1891.72,1471.17 1891.72,1530.04 ; 1891.72,1566.57 1891.72,1530.04 ; v1(2023.87,1529.85) 1891.91,1529.85 1891.72,1530.04 ; v1@2166.77,1498.15 2168,1496.92 2168,1496.8 2199.3,1465.5 2370.32,1465.5 CN3.1@2473.26,1362.56 2656.56,1362.56 JP2.1@2667,1352.13 2667,1426.61 ; JP3.2@2255,3068 2258.91,3064.09 2258.91,2972.91 ; CN1.1@2472.94,1106.94 CN3.1@2472.94,1362.24 ; CN1.1@2476.04,1111.26 2497.46,1093 2740.9,1093 2758.72,1075.18 2758.72,1054.92 ; v1(2525,3465) 2525,3233 ; v1@2593,3233 2525,3233 ; 2677.64,1426.61 2667,1426.61 ; 2258.91,2972.91 1886.02,2600.02 1886.02,2207.59 2667,1426.61 ; 2258.91,2972.91 2357.91,2972.91 2525,3140 2525,3233
  other v1: 2166,1500
TVDD*: JP1.2 R33.1 | length 129
  Top Layer w20: JP1.2@1689,753 1693.73,753 1756.08,690.65 1756.08,654.52
TVDD_DISCHARGE_EN: R18.2 U15.25 | length 404.9
  Top Layer w6: R18.2@1755.53,507.78 1802.51,507.78 1821.48,526.75 1821.48,583.55 1888.58,650.66 1957.61,650.66 1997,611.27 U15.25@2051.68,611.27
USB_DM: R10.2 U15.32 | length 536.9
  Top Layer w6: R10.2@1604,258 1660.4,314.4 1812.28,314.4 1971.36,473.47 U15.32@2051.68,473.47
USB_DP: R11.2 U15.33 | length 471.3
  Top Layer w6: R11.2@1661.5,258 1698.45,294.95 1825.73,294.95 1984.56,453.79 U15.33@2051.68,453.79
VBUS_PYLK: FUSE1.1 U6.5 USB1.A4 USB1.A9 USB1.B4 USB1.B9 | length 748.3
  Top Layer w10: USB1.A4@2128.81,32.89 USB1.B9@2140.62,32.89 ; USB1.B4@2317.78,32.88 USB1.A9@2329.6,32.88
  Top Layer w20: U6.5@1922.15,33 1922.98,32.17 1963.58,32.17 v2(1964.2,31.55) ; USB1.B9@2135.05,50.56 v4@2135.05,94.45 ; USB1.A9@2323.87,52.86 v4@2323.87,86.67
  Bottom Layer w15: 1933.39,148.39 FUSE1.1@1903,148.39 1912,139.39 1912,120 1964.2,67.8 v2(1964.2,31.55)
  Bottom Layer w20: v4@2331.13,95.01 v4(2331.62,95.5)
  Bottom Layer w30: FUSE1.1@1903,148.39 FUSE1.1@1911.66,157.06 ; 1933.39,148.39 2081.11,148.39 v4(2134,95.5) ; v4@2134.49,95.01 2279.68,95.01 ; 2279.68,96.41 v4@2330.72,96.41
VCCA: C30.2 C42.1 CN4.13 L1.2 U18.13 | length 1059
  Top Layer w8: U18.13@2342.58,2230.63 2342.58,2178.95 2429.53,2092 2879.72,2092 2905.71,2066.01 2999.14,2066.01 3050.14,2117 CN4.13@3060,2117
  Top Layer w10: U18.13@2342.58,2230.63 2342.58,2309.63 v1(2344.18,2311.23)
  Bottom Layer w15: v1(2344.18,2311.23) 2344.18,2341.35 C30.2@2340.94,2344.58 2340.51,2345.01 C42.1@2340.51,2394.65 2340.63,2394.53 L1.2@2396.29,2394.53
VDD: C26.1 C32.2 C33.2 CN4.32 CN5.1 JP2.2 L1.1 R58.2 U18.32 U18.64 | length 3902.2
  Top Layer w10: CN5.1@1525,1517 1565.14,1517 1854.55,1806.41 1854.55,2005.53 1997.86,2148.83 C32.2@1997.86,2189.8 1997.86,2309.36 U18.64@2027.63,2309.36
  Top Layer w15: C32.2@1998.22,2190.17 2048.15,2190.17 v1(2048.93,2190.95)
  Top Layer w20: U18.32@2454.27,2609.19 2511.29,2609.19 2551.69,2649.59 2551.69,2700.77 C26.1@2549.22,2703.24 v1(2549.22,2743.17) 2823.05,3017 CN4.32@2960,3017
  Bottom Layer w20: v1(2048.93,2190.95) 2547.79,2190.95 2549.22,2189.52 ; L1.1@2459.28,2394.53 2549.22,2394.53 ; v1(2549.22,2743.17) 2549.22,2394.53 ; 2737.64,1426.61 2729.62,1434.62 2729.62,1527.16 2729.62,2009.12 2549.22,2189.52 ; 2745.52,1434.48 2754.76,1425.24 2754.76,1375.19 2767,1362.95 JP2.2@2767,1352.13 ; 2549.22,2189.52 2549.22,2394.53
VSSA: C30.1 C42.2 CN4.12 R60.1 U18.12 | length 1008.8
  Top Layer w8: v1(2288.81,2309.61) 2291.73,2309.61 2322.9,2278.44 2322.9,2176.01 2432.65,2066.26 2580.5,2066.26 2582,2064.76 ; 2582,2066.26 2871.13,2066.26 2910.68,2026.7 2950.3,2026.7 CN4.12@2960,2017
  Bottom Layer w15: 2212.63,2393.15 2277.01,2393.15 C42.2@2278.51,2394.65 2278.51,2345.01 C30.1@2278.94,2344.58 2288.81,2334.71 v1(2288.81,2309.61)
pads on no net: U15.42 U15.45 U21. U21.A8 U21.B8 USB1. USB1.A8 USB1.B8

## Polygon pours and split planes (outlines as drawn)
GND on Bottom Layer "NONET_L-01_P-001" (solid, remove dead copper, pour order 3): 1359.13,3648.12 3124,3648.12 3124,-277 1350.51,-277
GND on Top Layer "NONET_L-01_P-001" (solid, remove dead copper, pour order 4): 1359.13,3648.12 3124,3648.12 3124,-277 1350.51,-277

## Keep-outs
Keep-Out Layer:
  lines w8: 1354,-198.26 ccw(c1432.74,-198.26) 1432.74,-277 3046.91,-277 ccw(c3046.91,-198.26) 3125.65,-198.26 3125.65,1196.35 ccw(c3084,1196.35) 3084,1238 2984,1238 cw(c3011.5,1265.5) 2984,1293 3084,1293 ccw(c3084,1334.65) 3125.65,1334.65 3125.65,3578.75 3125.65,3598.12 ccw(c3075.65,3598.12) 3075.65,3648.12 3046.91,3648.12 1432.74,3648.12 1404,3648.12 ccw(c1404,3598.12) 1354,3598.12 1354,3582.09 1354,1338 ccw(c1397.75,1336.75) 1396.5,1293 1496.5,1293 cw(c1469,1265.5) 1496.5,1238 1396.5,1238 ccw(c1397.75,1194.25) 1354,1193 1354,-198.26 ; 1569,1238 cw(c1596.5,1265.5) 1569,1293 1919,1293 1939,1293 cw(c1911.5,1265.5) 1939,1238 1919,1238 1569,1238 ; 2614,1238 cw(c2641.5,1265.5) 2614,1293 2634,1293 2914,1293 cw(c2886.5,1265.5) 2914,1238 2634,1238 2614,1238

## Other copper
Top Layer:
  region net 3.3V_OUT: 1759,3150 1814,3150 1820,3144 1820,3088 1810,3078 1761,3078 1752,3087 1752,3143
  pour cut-out: 3009,1093 3019,1093 3019,1083 3009,1083
  pour cut-out: 1629,213 1639,213 1639,203 1629,203
  pour cut-out: 1629,248 1639,248 1639,238 1629,238
  pour cut-out: 1684,248 1689.5,248 1689.5,226 1684,226
  pour cut-out: 1684,213 1694,213 1694,203 1684,203
  region net 5V_USB_CHGR: 1739,-42 1749,-32 1774,-32 1819,-77 1864,-77 1884,-97 2014,-97 2014,-157 1869,-157 1869,-137 1844,-112 1789,-112 1754,-77 1739,-62
  region net 3V3_PYLK: 1594,38 1644,38 1664,18 1709,18 1714,13 1714,-27 1699,-42 1699,-112 1716.5,-129.5 1709,-137 1647.39,-137 1647.39,-123.51 1659,-111.9 1659,-47 1634,-22 1594,-22
  region net 3V3_PYLK: 2449,-122 2459,-112 2479,-112 2489,-122 2489,-147 2494,-152 2539,-152 2544,-157 2544,-172 2539,-177 2484,-177 2449,-142
  region net 3V3_USB_PYLK: 2581.5,-157 2654,-157 2669,-142 2689,-142 2699,-152 2699,-172 2684,-187 2669,-187 2644,-212 2644,-252 2579,-252 2579,-158.67
  pour cut-out: 1744,218 1754,218 1754,208 1744,208
  pour cut-out: 1799,218 1809,218 1809,208 1799,208
  pour cut-out: 2981.43,760 2991.43,760 2991.43,750 2981.43,750
  pour cut-out: 3029,798 3039,798 3039,788 3029,788
Bottom Layer:
  region net 3.3V_OUT: 1707,3019 1748,3019 1762,3005 1809,3005 1817,3013 1817,3191 1806,3202 1770,3202 1755,3187 1755,3067 1739,3051 1705,3051 1695,3041 1695,3031
  region net NetC38_2: 1876,3126 1876,3151 1881,3156 1957,3156 2009,3208 2009,3225 2059,3225 2066,3218 2066,3134 1998,3134 1958,3094 1958,3018 1954,3014 1904,3014 1890,3000 1840,3000 1840,3058 1847,3065 1919,3065 1919,3115 1912,3122 1880,3122

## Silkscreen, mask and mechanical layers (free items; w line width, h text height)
Top Overlay:
  drawing of 1057 lines, arcs and shapes, not listed
  text "USER_PB0" at 1449,3288.66 h60
  text "NRST" at 2819,3288.64 h60
  text "VDD*" at 2207,3120 h50
  text "5V" at 2334,3119.54 h50
  text "3V3" at 2106,3117.54 h50
  text "33" at 1405,3080.54 h50
  text "34" at 1508,3080.54 h50
  text "31" at 3043,3079.54 h50
  text "32" at 2942,3077.54 h50
  text "VDD" at 2661,3003.19 h55
  text "GND" at 2777.41,3002.59 h55
  text "B13" at 1731.35,3001.58 h55
  text "B12" at 1596,3001 h55
  text "VDD_SEL" at 2151,2984.89 h50
  text "B11" at 2682,2903.8 h55
  text "B10" at 2799.91,2902.6 h55
  text "B14" at 1596,2901.4 h55
  text "B15" at 1731.08,2901.31 h55
  text "PY32F040-START V2.0" at 2020,2890.17 h65
  text "2025-03" at 2200.95,2805.47 h65
  text "B2" at 2682,2804.41 h55
  text "B1" at 2833.87,2803.2 h55
  text "C6" at 1596,2800.75 h55
  text "C7" at 1744.77,2800.51 h55
  text "B0" at 2682,2704.44 h55
  text "C5" at 2822.93,2702.73 h55
  text "C8" at 1596,2700.09 h55
  text "C9" at 1744.7,2699.7 h55
  text "C4" at 2682,2603.99 h55
  text "A7" at 2823.42,2603.45 h55
  text "A8" at 1595.96,2599.91 h55
  text "A9" at 1744.91,2599.38 h55
  text "A6" at 2681.96,2504.01 h55
  text "A5" at 2823.14,2503.6 h55
  text "A10" at 1595.96,2499.73 h55
  text "A11" at 1734.47,2499.63 h55
  text "A4" at 2681.96,2404.75 h55
  text "F4" at 2830.39,2404.32 h55
  text "A12" at 1595.96,2400.13 h55
  text "A13" at 1727.68,2399.21 h55
  text "F3" at 2682,2304.67 h55
  text "A3" at 2823.42,2304.24 h55
  text "F5" at 1596,2300.09 h55
  text "F6" at 1754,2298.59 h55
  text "A2" at 2681.96,2205.33 h55
  text "A1" at 2830.2,2204.88 h55
  text "A14" at 1595.96,2200.49 h55
  text "A15" at 1727.4,2198.62 h55
  text "A0" at 2660.96,2105.36 h55
  text "VCCA" at 2745,2104.42 h55
  text "C10" at 1596,2099.83 h55
  text "C11" at 1734.25,2097.81 h55
  text "VSSA" at 2661,2004.91 h55
  text "C3" at 2823.21,2003.85 h55
  text "C12" at 1596,1999.17 h55
  text "F7" at 1749.83,1998.19 h55
  text "C2" at 2681,1904.45 h55
  text "C1" at 2829.99,1903.43 h55
  text "B3" at 1596,1898.89 h55
  text "B4" at 1746.79,1898.58 h55
  text "C0" at 2681,1803.99 h55
  text "F2" at 2830.62,1804.02 h55
  text "B5" at 1596,1798.89 h55
  text "B6" at 1746.66,1798.26 h55
  text "F1" at 2685,1705 h55
  text "F0" at 2830.39,1704.04 h55
  text "B7" at 1596,1699.42 h55
  text "F8" at 1749.76,1697.94 h55
  text "C15" at 2672,1604.15 h55
  text "C14" at 2796.03,1603.57 h55
  text "B8" at 1596,1599.25 h55
  text "B9" at 1746.58,1597.62 h55
  text "C13" at 2672,1503.59 h55
  text "F9" at 2830.19,1503.59 h55
  text "GND" at 1596,1498.59 h55
  text "VDD" at 1712,1498 h55
  text "NRST" at 2088.41,1431 h55 r90
  text "SWC" at 2189.71,1431 h55 r90
  text "GND" at 2291.01,1431 h55 r90
  text "SWD" at 2392.31,1431 h55 r90
  text "VDD*" at 2493,1431 h55 r90
  text "2" at 2947.96,1422 h50
  text "1" at 3050,1422 h50
  text "64" at 1502,1420.54 h50
  text "63" at 1404,1420.49 h50
  text "BOOT0" at 1707,1406.22 h45
  text "GND" at 1587,1402.98 h50
  text "VDD*" at 1871,1403 h50
  text "VDD*" at 2621,1402.51 h45
  text "VDD" at 2730,1402.51 h45
  text "IDD" at 2822,1342 h45
  text "BOOT_SEL" at 1439.63,1327.3 h40
  text "NRST" at 2004,1171.48 h45
  text "SWC" at 2127.88,1171.48 h45
  text "GND" at 2236.55,1171.48 h45
  text "SWD" at 2339.91,1171.48 h45
  text "VDD*" at 2448,1171 h45
  text "SWO" at 1996,899.47 h55
  text "RTS" at 2129,899.47 h55
  text "DTR" at 2234,898.88 h55
  text "TX" at 2350.31,898.88 h55
  text "RX" at 2444,898.88 h55
  text "5V" at 1544,798.64 h60
  text "3V3" at 1764,798.64 h60
  text "VDD*" at 1619,798 h60
  text "BT0" at 2489.46,137 h50 r90
  text "VDD" at 2587.9,137 h50 r90
  text "DIO" at 2687.42,137 h50 r90
  text "GND" at 2786.94,137 h50 r90
  text "CLK" at 2886.46,137 h50 r90
  text "PY-LINK V2.0" at 2051.04,120.23 h65
Bottom Overlay:
Mechanical 1:
  lines w6: 1569,1238 1919,1238 1939,1238 ; 1569,1293 1919,1293 1939,1293 ; 2614,1238 2634,1238 2914,1238 ; 2614,1293 2634,1293 2914,1293
  lines w8: 1569,1238 cw(c1596.5,1265.5) 1569,1293 ; 1939,1238 ccw(c1911.5,1265.5) 1939,1293 ; 2614,1238 cw(c2641.5,1265.5) 2614,1293 ; 2914,1238 ccw(c2886.5,1265.5) 2914,1293

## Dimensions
1396.5,1293 to 1432.74,3648.12 on Mechanical 1
3124,-277 to 3190,3649 on Mechanical 1
1432.74,-277 to 1349,1228 on Mechanical 1
1354,-277 to 3124,-337 on Mechanical 1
